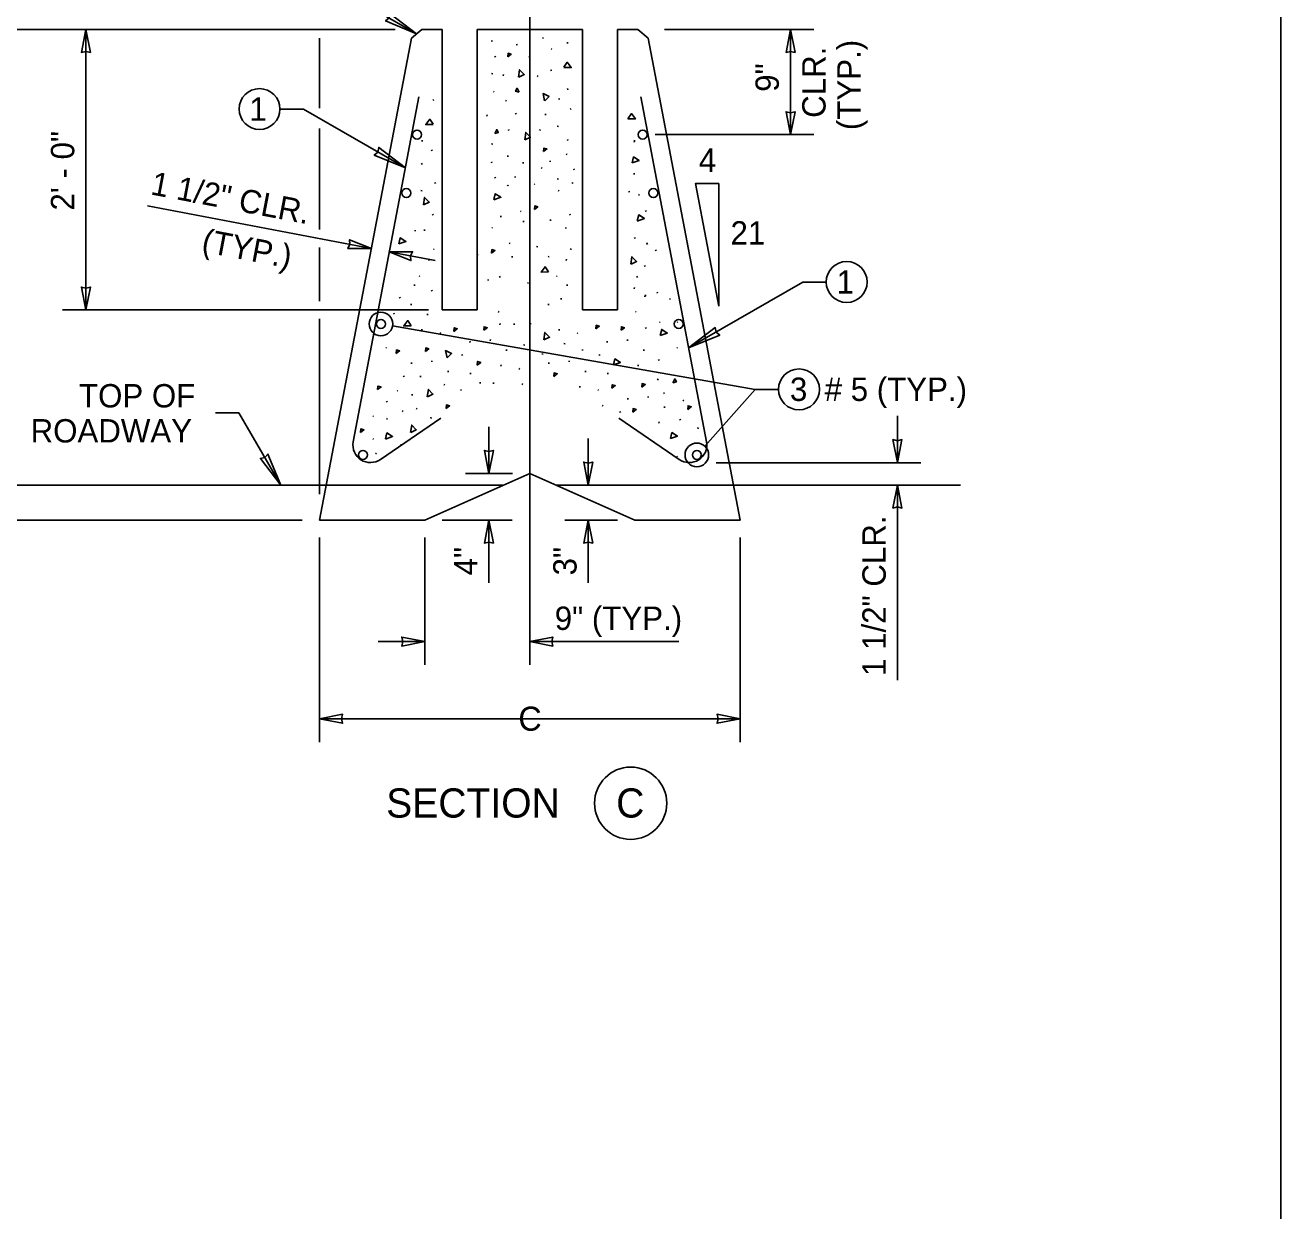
# Model space of a CAD drawing. Extents: x 99862 to 103151, y 100000 to 102076.
# Drawn here: x 102291 to 103151, y 100549 to 101361 of the extents above; entities that cross this region are included whole.
import ezdxf

# ---------------------------------------------------------------- set-up
doc = ezdxf.new("R2010")
doc.units = 0
for name, color, linetype in [('Level 1', 7, 'Continuous'), ('Level 10', 7, 'Continuous'), ('Level 13', 7, 'Continuous'), ('Level 15', 7, 'Continuous'), ('Level 16', 7, 'Continuous'), ('Level 2', 7, 'Continuous'), ('Level 20', 7, 'Continuous'), ('Level 9', 7, 'Continuous')]:
    doc.layers.add(name, color=color, linetype=linetype)

msp = doc.modelspace()

# ---------------------------------------------------------------- linework, layer by layer
at = {"layer": 'Level 1'}
msp.add_lwpolyline([(99862, 99999.5), (103151, 99999.5), (103151, 102075.5), (99862, 102075.5)], close=True, dxfattribs=at)
at = {"layer": 'Level 10'}
for p, q in [((102560.7, 101311.91), (102515.67, 101075.51)), ((102712.63, 101311.91), (102757.66, 101075.51)), ((102534.34, 101063.56), (102575.81, 101091.76)), ((102739, 101063.56), (102697.52, 101091.76))]:
    msp.add_line(p, q, dxfattribs=at)
for centre in [(102559.44, 101285.98), (102713.89, 101285.98), (102552.09, 101246), (102721.24, 101246), (102534.66, 101156.33), (102738.67, 101156.33), (102522.3, 101066.67), (102751.03, 101066.67)]:
    msp.add_circle(centre, 3.08, dxfattribs=at)
for centre, start, end in [((102527.49, 101073.42), 169.95883, 304.80379), ((102745.85, 101073.42), 235.19621, 10.04117)]:
    msp.add_arc(centre, 12, start, end, dxfattribs=at)
at = {"layer": 'Level 13'}
for p, q in [((102645.22, 101352), (102645.99, 101352.21)), ((102610.21, 101350.11), (102610.98, 101350.32)), ((102627.39, 101347.59), (102628.17, 101347.8)), ((102651.16, 101344.82), (102651.67, 101344.44)), ((102662.41, 101348.45), (102662.35, 101349.33)), ((102612.7, 101339.75), (102613.06, 101339.03)), ((102636.03, 101339.26), (102636.81, 101339.47)), ((102611.21, 101327.55), (102610.43, 101327.77)), ((102618.48, 101326.26), (102618.54, 101327.13)), ((102641.78, 101326.18), (102642.3, 101325.8)), ((102650.91, 101329.93), (102651.68, 101330.14)), ((102662.38, 101317.49), (102662.74, 101316.77)), ((102570.14, 101309.66), (102570.92, 101309.87)), ((102611.78, 101315.6), (102612.3, 101315.22)), ((102620.66, 101309.25), (102619.89, 101309.47)), ((102657.13, 101310.29), (102656.28, 101310.52)), ((102626.89, 101300.77), (102627.25, 101300.05)), ((102647.4, 101299.31), (102647.46, 101300.18)), ((102664.17, 101303.38), (102664.94, 101303.59)), ((102607.31, 101298.57), (102607.37, 101299.44)), ((102656.22, 101291.47), (102655.44, 101291.69)), ((102622.02, 101289.58), (102622.38, 101288.86)), ((102643.59, 101288.75), (102643.65, 101289.62)), ((102662.38, 101282.72), (102662.74, 101282)), ((102562.86, 101281.32), (102562.92, 101282.19)), ((102569.32, 101275.56), (102569.67, 101274.84)), ((102611.21, 101279.48), (102610.43, 101279.69)), ((102708.19, 101280.88), (102708.25, 101281.75)), ((102708.22, 101281.32), (102708.28, 101282.19)), ((102562.5, 101266.35), (102562.86, 101265.63)), ((102610.32, 101267.31), (102610.67, 101266.59)), ((102621.49, 101270.74), (102621.55, 101271.61)), ((102632.07, 101266.28), (102632.13, 101267.16)), ((102650.47, 101267.25), (102650.53, 101268.12)), ((102662.21, 101272.41), (102661.43, 101272.62)), ((102612.7, 101256.86), (102613.06, 101256.14)), ((102626.55, 101256.53), (102626.61, 101257.4)), ((102644.51, 101263.35), (102645.03, 101262.97)), ((102666.69, 101262.63), (102667.05, 101261.91)), ((102708.15, 101258.75), (102708.21, 101259.63)), ((102571.66, 101253.21), (102572.02, 101252.49)), ((102621.16, 101251.35), (102621.67, 101250.97)), ((102621.56, 101251.28), (102622.08, 101250.9)), ((102639.56, 101252.31), (102640.08, 101251.93)), ((102656.22, 101255.39), (102655.44, 101255.61)), ((102665.67, 101253.21), (102666.02, 101252.49)), ((102562.83, 101247.44), (102561.98, 101247.66)), ((102656.83, 101247.44), (102655.98, 101247.66)), ((102704.27, 101246.91), (102705.12, 101247.13)), ((102711.16, 101245.02), (102711.68, 101244.64)), ((102570.03, 101231.52), (102570.38, 101230.79)), ((102630.18, 101233.67), (102630.7, 101233.29)), ((102664.03, 101231.52), (102664.38, 101230.79)), ((102715.9, 101233.97), (102716.26, 101233.25)), ((102610.64, 101222.36), (102611.15, 101221.98)), ((102616.72, 101229.55), (102616.78, 101230.42)), ((102632.33, 101226.11), (102632.39, 101226.98)), ((102650.73, 101227.07), (102650.79, 101227.94)), ((102661.25, 101221.62), (102661.31, 101222.49)), ((102558.03, 101219.78), (102558.09, 101220.65)), ((102564.43, 101220.14), (102564.49, 101221.01)), ((102708.4, 101215.56), (102708.76, 101214.84)), ((102570.66, 101207.81), (102571.18, 101207.43)), ((102623.23, 101211.37), (102622.45, 101211.58)), ((102642.1, 101209.23), (102641.26, 101209.46)), ((102664.26, 101207.88), (102664.78, 101207.5)), ((102664.67, 101207.81), (102665.18, 101207.43)), ((102717.23, 101211.37), (102716.45, 101211.58)), ((102716.89, 101211.55), (102717.25, 101210.83)), ((102722.72, 101207.04), (102723.08, 101206.32)), ((102567.59, 101199.9), (102567.65, 101200.78)), ((102600.86, 101203.79), (102601.37, 101203.41)), ((102624.56, 101201.84), (102624.62, 101202.71)), ((102649.14, 101202.32), (102649.91, 101202.53)), ((102661.59, 101199.9), (102661.65, 101200.78)), ((102715.22, 101196.47), (102715.58, 101195.75)), ((102560.88, 101189.24), (102561.4, 101188.86)), ((102615.96, 101188.96), (102616.32, 101188.24)), ((102654.89, 101189.24), (102655.4, 101188.86)), ((102709.97, 101188.96), (102710.32, 101188.24)), ((102557.63, 101182.49), (102557.69, 101183.36)), ((102569.32, 101179.43), (102569.67, 101178.71)), ((102608.07, 101185.99), (102608.14, 101186.86)), ((102634.98, 101184.34), (102635.82, 101184.56)), ((102662.21, 101182.49), (102662.27, 101183.36)), ((102708.19, 101180.4), (102708.25, 101181.27)), ((102547.5, 101174.65), (102547.86, 101173.93)), ((102658.03, 101173.08), (102658.09, 101173.95)), ((102715.43, 101174.83), (102715.37, 101175.7)), ((102715.75, 101175.47), (102715.81, 101176.35)), ((102723.74, 101178.06), (102724.1, 101177.34)), ((102732.4, 101173.61), (102732.91, 101173.23)), ((102543.41, 101163.74), (102543.77, 101163.02)), ((102555.39, 101169.29), (102555.45, 101170.16)), ((102566.51, 101162.37), (102566.57, 101163.25)), ((102615.04, 101164.81), (102615.56, 101164.43)), ((102649.39, 101169.29), (102649.45, 101170.16)), ((102696.67, 101166.36), (102696.73, 101167.23)), ((102709.05, 101164.81), (102709.56, 101164.43)), ((102616.2, 101155.82), (102616.26, 101156.7)), ((102625.93, 101155.82), (102625.99, 101156.7)), ((102637.51, 101156.5), (102636.66, 101156.73)), ((102715.9, 101153.86), (102716.26, 101153.14)), ((102725.5, 101157.75), (102726.01, 101157.37)), ((102737.5, 101157.75), (102738.01, 101157.37)), ((102562.7, 101151.81), (102562.76, 101152.68)), ((102575.07, 101150.26), (102575.59, 101149.88)), ((102609.55, 101144.86), (102609.61, 101145.73)), ((102656.7, 101151.81), (102656.76, 101152.68)), ((102669.07, 101150.26), (102669.59, 101149.88)), ((102703.55, 101144.86), (102703.61, 101145.73)), ((102538.04, 101140.16), (102538.56, 101139.78)), ((102595.62, 101143.66), (102595.68, 101144.53)), ((102620.67, 101137.94), (102620.73, 101138.81)), ((102633.17, 101141.79), (102632.33, 101142.01)), ((102660.83, 101142.8), (102659.98, 101143.03)), ((102672.67, 101138.05), (102672.73, 101138.92)), ((102689.62, 101143.66), (102689.68, 101144.53)), ((102714.67, 101137.94), (102714.73, 101138.81)), ((102737.22, 101140.16), (102737.74, 101139.78)), ((102555.65, 101129.11), (102555.71, 101129.99)), ((102569.58, 101130.31), (102569.64, 101131.18)), ((102590.18, 101135.43), (102590.54, 101134.71)), ((102616.86, 101127.38), (102616.92, 101128.25)), ((102645.73, 101135.62), (102644.89, 101135.85)), ((102649.65, 101129.11), (102649.71, 101129.99)), ((102663.58, 101130.31), (102663.64, 101131.18)), ((102684.18, 101135.43), (102684.54, 101134.71)), ((102710.86, 101127.38), (102710.92, 101128.25)), ((102724.76, 101132.04), (102725.12, 101131.32)), ((102550.21, 101120.88), (102550.57, 101120.16)), ((102561.73, 101119.82), (102561.67, 101120.7)), ((102580.69, 101123.39), (102580.76, 101124.27)), ((102595.96, 101121.94), (102596.02, 101122.82)), ((102629.23, 101125.83), (102629.75, 101125.45)), ((102674.7, 101123.39), (102674.76, 101124.27)), ((102689.97, 101121.94), (102690.03, 101122.82)), ((102545.8, 101110.67), (102546.32, 101110.29)), ((102578.55, 101114.69), (102577.7, 101114.92)), ((102589.26, 101111.28), (102589.78, 101110.9)), ((102602.6, 101115.56), (102602.66, 101116.43)), ((102611.82, 101115.28), (102611.88, 101116.15)), ((102631.25, 101115.31), (102631.77, 101114.93)), ((102670.89, 101112.83), (102670.95, 101113.7)), ((102683.26, 101111.28), (102683.78, 101110.9)), ((102723.78, 101118.59), (102724.29, 101118.22)), ((102724.18, 101118.53), (102724.69, 101118.15)), ((102538.55, 101103.41), (102538.91, 101102.69)), ((102555.99, 101107.4), (102556.05, 101108.27)), ((102703.81, 101104.68), (102703.87, 101105.55)), ((102717.74, 101105.88), (102717.8, 101106.75)), ((102741.54, 101104.12), (102742.05, 101103.74)), ((102529.08, 101093.42), (102529.59, 101093.04)), ((102549.29, 101096.73), (102549.8, 101096.36)), ((102559.58, 101098.14), (102558.73, 101098.36)), ((102686.96, 101100.28), (102686.12, 101100.51)), ((102698.37, 101096.45), (102698.73, 101095.73)), ((102728.86, 101098.96), (102728.92, 101099.83)), ((102538.56, 101091.53), (102539.08, 101091.15)), ((102568.81, 101092.41), (102569.16, 101091.69)), ((102725.05, 101088.4), (102725.11, 101089.27)), ((102739.42, 101091.13), (102739.78, 101090.41)), ((102751.61, 101085.33), (102751.97, 101084.61)), ((102529.08, 101077.73), (102529.59, 101077.35)), ((102531.06, 101067.84), (102531.57, 101067.46)), ((102548.44, 101073.92), (102548.8, 101073.2)), ((102737.31, 101065.81), (102737.83, 101065.43))]:
    msp.add_line(p, q, dxfattribs=at)
for points in [[(102621.5, 101339.28), (102621.74, 101341.73), (102623.86, 101341.08), (102621.5, 101339.28)], [(102659.9, 101332.02), (102665.03, 101331.92), (102662.28, 101335.58), (102659.95, 101332.1)], [(102628.93, 101325.34), (102629.64, 101330.42), (102632.82, 101327.13), (102629.02, 101325.37)], [(102629.29, 101315.04), (102626.93, 101315.74), (102627.97, 101317.7), (102629.29, 101315.04)], [(102646.75, 101309.06), (102645.68, 101314.07), (102649.79, 101312.07), (102646.82, 101309.11)], [(102703.8, 101296.84), (102708.92, 101296.74), (102706.17, 101300.4), (102703.84, 101296.92)], [(102570.48, 101292.99), (102565.36, 101292.89), (102568.11, 101296.55), (102570.44, 101293.07)], [(102612.64, 101286.82), (102615, 101287.53), (102613.96, 101289.49), (102612.64, 101286.82)], [(102633.15, 101282.39), (102633.85, 101287.47), (102637.03, 101284.18), (102633.23, 101282.42)], [(102646.01, 101274.37), (102646.25, 101276.82), (102648.38, 101276.17), (102646.01, 101274.37)], [(102706.64, 101266.57), (102711.49, 101268.23), (102707.66, 101270.72), (102706.65, 101266.66)], [(102563.85, 101237.96), (102564.55, 101243.04), (102567.73, 101239.75), (102563.93, 101237.99)], [(102612, 101241.4), (102616.85, 101243.06), (102613.02, 101245.55), (102612.01, 101241.48)], [(102639.74, 101234.69), (102639.98, 101237.14), (102642.1, 101236.5), (102639.74, 101234.69)], [(102710.25, 101226.81), (102715.09, 101228.47), (102711.26, 101230.97), (102710.26, 101226.9)], [(102546.92, 101211.21), (102551.77, 101212.87), (102547.94, 101215.37), (102546.94, 101211.3)], [(102610.41, 101204.81), (102610.65, 101207.26), (102612.78, 101206.62), (102610.41, 101204.81)], [(102705.87, 101197.26), (102706.58, 101202.33), (102709.76, 101199.05), (102705.96, 101197.29)], [(102649.46, 101191.93), (102644.33, 101191.84), (102647.08, 101195.49), (102649.41, 101192.01)], [(102555.45, 101155.08), (102550.33, 101154.98), (102553.08, 101158.63), (102555.41, 101155.15)], [(102584.62, 101151.28), (102584.87, 101153.73), (102586.99, 101153.09), (102584.62, 101151.28)], [(102605.09, 101151.98), (102605.33, 101154.43), (102607.45, 101153.78), (102605.09, 101151.98)], [(102681.87, 101152.95), (102682.11, 101155.41), (102684.24, 101154.76), (102681.87, 101152.95)], [(102699.09, 101151.98), (102699.33, 101154.43), (102701.46, 101153.78), (102699.09, 101151.98)], [(102646.26, 101145.45), (102646.96, 101150.53), (102650.14, 101147.25), (102646.34, 101145.48)], [(102725.93, 101148.41), (102730.78, 101150.07), (102726.95, 101152.56), (102725.94, 101148.5)], [(102545.1, 101136.11), (102545.34, 101138.57), (102547.47, 101137.92), (102545.1, 101136.11)], [(102565.12, 101137.43), (102565.36, 101139.88), (102567.48, 101139.23), (102565.12, 101137.43)], [(102580.04, 101133.14), (102578.97, 101138.15), (102583.08, 101136.15), (102580.11, 101133.2)], [(102600.65, 101128.2), (102600.89, 101130.65), (102603.01, 101130.01), (102600.65, 101128.2)], [(102693.86, 101128.28), (102698.71, 101129.94), (102694.88, 101132.43), (102693.88, 101128.36)], [(102653.01, 101120.41), (102653.25, 101122.86), (102655.37, 101122.22), (102653.01, 101120.41)], [(102532.39, 101111.37), (102532.63, 101113.82), (102534.76, 101113.17), (102532.39, 101111.37)], [(102566.44, 101106.47), (102567.14, 101111.55), (102570.32, 101108.27), (102566.52, 101106.5)], [(102692.81, 101112.3), (102693.06, 101114.75), (102695.18, 101114.11), (102692.81, 101112.3)], [(102713.28, 101113), (102713.52, 101115.45), (102715.64, 101114.8), (102713.28, 101113)], [(102734.63, 101116.08), (102736.99, 101116.78), (102735.95, 101118.75), (102734.63, 101116.08)], [(102728.77, 101109.26), (102728.27, 101108.77)], [(102579.3, 101098.45), (102579.54, 101100.9), (102581.67, 101100.25), (102579.3, 101098.45)], [(102707.17, 101095.98), (102707.41, 101098.43), (102709.53, 101097.79), (102707.17, 101095.98)], [(102744.8, 101097.83), (102745.04, 101100.28), (102747.17, 101099.64), (102744.8, 101097.83)], [(102555.03, 101082.04), (102555.73, 101087.12), (102558.91, 101083.84), (102555.11, 101082.07)], [(102520.61, 101081.97), (102520.86, 101084.42), (102522.98, 101083.77), (102520.61, 101081.97)], [(102537.76, 101077.5), (102542.6, 101079.16), (102538.77, 101081.66), (102537.77, 101077.59)], [(102732.92, 101077.84), (102737.76, 101079.5), (102733.93, 101082), (102732.93, 101077.93)]]:
    msp.add_lwpolyline(points, dxfattribs=at)
at = {"layer": 'Level 15'}
for p, q in [((102559.11, 101355.06), (102473.57, 101404.44)), ((102636.66, 101373.99), (102636.66, 100922.79)), ((102544.46, 101357.99), (102160.67, 101357.97)), ((102332.67, 101357.98), (102332.67, 101165.9)), ((102492.67, 101351.99), (102492.67, 101304.02)), ((102728.87, 101357.98), (102831.19, 101357.98)), ((102815.19, 101357.98), (102815.19, 101285.98)), ((102465.54, 101303.52), (102481.54, 101303.52)), ((102551.42, 101263.18), (102481.54, 101303.52)), ((102492.67, 101290.16), (102492.67, 101220.92)), ((102722.58, 101285.98), (102831.19, 101285.98)), ((102528.11, 101208.06), (102374.82, 101237.26)), ((102492.67, 101208.7), (102492.67, 101171.9)), ((102571.74, 101199.75), (102540.31, 101205.74)), ((102745.4, 101139.89), (102823.63, 101185.06)), ((102839.63, 101185.06), (102823.63, 101185.06)), ((102567.2, 101165.9), (102316.67, 101165.9)), ((102492.67, 101159.9), (102492.67, 101039.68)), ((102790.99, 101111.5), (102806.99, 101111.5)), ((102437.46, 101095.58), (102421.46, 101095.58)), ((102466.09, 101045.99), (102437.46, 101095.58)), ((102888.41, 101061.38), (102888.41, 101093.38)), ((102608.67, 101053.99), (102608.67, 101085.99)), ((102676.69, 101045.99), (102676.69, 101077.99)), ((102764.37, 101061.29), (102904.5, 101061.29)), ((102624.67, 101053.99), (102592.67, 101053.99)), ((102888.39, 101045.99), (102888.39, 100912.29)), ((102480.67, 101021.99), (102160.69, 101021.98)), ((102576.67, 101021.99), (102624.66, 101021.99)), ((102608.67, 101021.99), (102608.67, 100979.01)), ((102660.67, 101021.99), (102696.67, 101021.99)), ((102676.67, 101021.99), (102676.67, 100979.01)), ((102708.67, 101021.99), (102780.67, 101021.99)), ((102492.67, 101009.99), (102492.67, 100870.01)), ((102564.67, 101009.99), (102564.67, 100922.79)), ((102780.67, 101009.99), (102780.67, 100870.01)), ((102564.67, 100938.79), (102532.67, 100938.79)), ((102738.71, 100938.79), (102636.66, 100938.79)), ((102492.67, 100886.01), (102780.67, 100886.01))]:
    msp.add_line(p, q, dxfattribs=at)
for points in [[(102559.11, 101355.06), (102537.84, 101363.89), (102540.25, 101365.95), (102540.83, 101369.06)], [(102332.67, 101357.98), (102329.59, 101342.25), (102332.67, 101342.98), (102335.76, 101342.25)], [(102815.19, 101357.98), (102812.1, 101342.25), (102815.19, 101342.98), (102818.27, 101342.25)], [(102815.19, 101285.98), (102812.1, 101301.7), (102815.19, 101300.97), (102818.27, 101301.7)], [(102551.42, 101263.18), (102533.14, 101277.18), (102532.56, 101274.06), (102530.15, 101272.01)], [(102528.11, 101208.06), (102512.08, 101207.97), (102513.38, 101210.87), (102513.24, 101214.03)], [(102540.31, 101205.74), (102556.33, 101205.82), (102555.04, 101202.93), (102555.18, 101199.76)], [(102332.67, 101165.9), (102329.59, 101181.62), (102332.67, 101180.89), (102335.76, 101181.62)], [(102745.4, 101139.9), (102763.68, 101153.9), (102764.25, 101150.78), (102766.66, 101148.73)], [(102888.41, 101061.38), (102891.5, 101077.1), (102888.41, 101076.37), (102885.33, 101077.1)], [(102608.67, 101053.99), (102611.75, 101069.72), (102608.67, 101068.99), (102605.58, 101069.72)], [(102466.09, 101045.99), (102457.26, 101067.26), (102455.2, 101064.85), (102452.09, 101064.27)], [(102676.69, 101045.99), (102679.77, 101061.72), (102676.69, 101060.99), (102673.6, 101061.72)], [(102888.39, 101045.99), (102891.48, 101030.27), (102888.39, 101031), (102885.31, 101030.27)], [(102608.67, 101021.99), (102611.75, 101006.27), (102608.67, 101007), (102605.58, 101006.27)], [(102676.67, 101021.99), (102679.75, 101006.27), (102676.67, 101007), (102673.58, 101006.27)], [(102564.67, 100938.79), (102548.94, 100935.71), (102549.67, 100938.79), (102548.94, 100941.88)], [(102636.66, 100938.79), (102652.38, 100935.71), (102651.65, 100938.79), (102652.38, 100941.88)], [(102492.67, 100886.01), (102508.39, 100882.92), (102507.66, 100886.01), (102508.39, 100889.09)], [(102780.67, 100886.01), (102764.94, 100882.92), (102765.67, 100886.01), (102764.94, 100889.09)]]:
    msp.add_lwpolyline(points, close=True, dxfattribs=at)
for points in [[(102766.05, 101168.51), (102766.05, 101252.51), (102750.05, 101252.51), (102766.05, 101168.51)], [(102542.63, 101154.94), (102790.99, 101111.5), (102756.41, 101072.7)]]:
    msp.add_lwpolyline(points, dxfattribs=at)
for centre in [(102534.66, 101156.33), (102751.03, 101066.67)]:
    msp.add_circle(centre, 8.08, dxfattribs=at)
at = {"layer": 'Level 16'}
msp.add_line((102931.58, 101045.99), (102776.1, 101045.99), dxfattribs=at)
msp.add_lwpolyline([(102497.24, 101045.99), (102238.3, 101045.99)], dxfattribs=at)
at = {"layer": 'Level 2'}
for p, q in [((102492.67, 101021.99), (102555.54, 101352.1)), ((102555.54, 101352.1), (102562.67, 101357.99)), ((102562.67, 101357.99), (102576.67, 101357.99)), ((102576.67, 101357.99), (102576.67, 101165.99)), ((102600.67, 101165.99), (102600.67, 101357.99)), ((102600.67, 101357.99), (102672.67, 101357.99)), ((102672.67, 101357.99), (102672.67, 101165.99)), ((102696.67, 101165.99), (102696.67, 101357.99)), ((102696.67, 101357.99), (102710.67, 101357.99)), ((102710.67, 101357.99), (102717.79, 101352.1)), ((102717.79, 101352.1), (102780.67, 101021.99)), ((102576.67, 101165.99), (102600.67, 101165.99)), ((102672.67, 101165.99), (102696.67, 101165.99)), ((102497.24, 101045.99), (102618.67, 101045.99)), ((102654.67, 101045.99), (102776.1, 101045.99)), ((102564.67, 101021.99), (102492.67, 101021.99)), ((102780.67, 101021.99), (102708.67, 101021.99))]:
    msp.add_line(p, q, dxfattribs=at)
msp.add_lwpolyline([(102708.67, 101021.99), (102636.67, 101053.99), (102564.67, 101021.99)], dxfattribs=at)
at = {"layer": 'Level 20'}
for centre in [(102451.54, 101303.52), (102853.63, 101185.06), (102820.99, 101111.5)]:
    msp.add_circle(centre, 14, dxfattribs=at)
at = {"layer": 'Level 9'}
msp.add_circle((102705.7, 100828.1), 24.75, dxfattribs=at)

# ---------------------------------------------------------------- texts
at = {"layer": 'Level 15'}
msp.add_text('C', height=16.5, dxfattribs=at).set_placement((102628.81, 100877.76))
at = {"layer": 'Level 20'}
for s, rotation, p in [('CLR.', 90, (102839.19, 101297.49)), ('(TYP.)', 90, (102863.19, 101289.09)), ('9"', 90, (102807.19, 101315.32)), ('2\' - 0"', 90, (102324.67, 101234)), ('1 1/2" CLR.    ', 349.21603, (102376.32, 101245.15)), ('       (TYP.)', 349.21603, (102370.34, 101213.71)), ('TOP OF', 360, (102327.91, 101099.16)), ('ROADWAY', 360, (102294.76, 101075.16)), ('1 1/2" CLR. ', 90, (102880.39, 100915.3)), ('4"', 90, (102600.67, 100984.13)), ('3"', 90, (102668.67, 100984.13))]:
    msp.add_text(s, height=16, rotation=rotation, dxfattribs=at).set_placement(p)
for s, height, p in [('1', 16, (102444.58, 101295.52)), ('4', 16, (102752.38, 101260.51)), ('21', 16, (102774.07, 101210.68)), ('1', 16, (102846.76, 101177.06)), (' 3  # 5 (TYP.)', 16, (102808.82, 101103.6)), ('9" (TYP.)', 16, (102653.71, 100946.79)), ('SECTION', 20, (102538.29, 100818.28)), ('C', 20, (102695.78, 100818.28))]:
    msp.add_text(s, height=height, dxfattribs=at).set_placement(p)

doc.saveas('drawing.dxf')
